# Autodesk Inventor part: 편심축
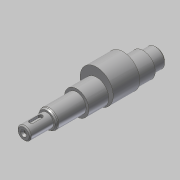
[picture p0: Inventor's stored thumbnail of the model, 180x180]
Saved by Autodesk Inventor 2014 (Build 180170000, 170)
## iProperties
Created: 2019-01
Part Number: 편심축
Material: 강철, 연강
Document SubType Name: Modeling
Designer: mduedu
Density: 7.86 g/cm^3
Appearance: 강철
Mass: 326.791 g
Surface Area: 90.982 cm^2
Volume: 41.5764 cm^3
Author: mduedu
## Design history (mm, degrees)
sketch "스케치1"
  geometry: L1 (0, 0)-(21, 0); L2 (21, 0)-(21, 6); L3 (21, 6)-(0, 6); L4 (0, 6)-(0, 0); L5 (21, 0)-(48, 0); L6 (48, 0)-(48, 8.5); L7 (48, 8.5)-(21, 8.5); L8 (21, 8.5)-(21, 0); L9 (48, 0)-(108, 0); L10 (108, 0)-(108, 11); L11 (108, 11)-(48, 11); L12 (48, 11)-(48, 0); L13 (108, 0)-(120, 0); L14 (120, 0)-(120, 8.5); L15 (120, 8.5)-(108, 8.5); L16 (108, 8.5)-(108, 0)
  constraints: 32 end point, 8 parallel, 4 horizontal, 4 perpendicular
  dimensions: "d0" = 120 distance between parallel lines of L14 L4; "d2" = 12 distance of L14.end L15.end; "d3" = 60 distance of L10.end L11.end; "d4" = 99 distance between parallel lines of L8 L14; "d5" = 12 diameter of L3 L1; "d6" = 17 diameter of L7 L5; "d7" = 17 diameter of L15 L13; "d8" = 22 diameter of L11 L9
revolve "회전1" sketch "스케치1" stored, may be unused: angle "d9" = 90 deg
node "작업 평면1"
sketch "스케치2"
  geometry: C1 r 15 at (0, 4); C2 r 11 at (0, 0) reference; 1 further point
  constraints: 1 centre point, 1 tangent, 1 vertical alignment
  dimensions: "d11" = 4 distance of point (0, 0) C1.centre
extrude "돌출1" join sketch "스케치2" distance "d12" = 24; taper "d13" = 0 deg
node "작업 평면2"
sketch "스케치3" dims "d16" = 12
  geometry: L1 (-4.5, 2)-(3.5, 2); L2 (3.5, 2)-(3.5, -2); L3 (3.5, -2)-(-4.5, -2); L4 (-4.5, -2)-(-4.5, 2); L5 (-10.5, 8.5)-(-10.5, -8.5) reference; 3 further points
  constraints: 8 end point, 2 midpoint, 2 parallel, 2 vertical alignment, 1 horizontal, 1 horizontal alignment, 1 perpendicular, 4 other
  dimensions: "d14" = 4 distance between parallel lines of L3 L1; "d17" = 4 dimension on L5
extrude "돌출2" cut sketch "스케치3" distance "d18" = 2.5; taper "d19" = 0 deg
chamfer "모따기1" distance "d20" = 1.82; stored, may be unused: second distance "d21" = 2, angle "d22" = 30 deg
fillet "모깎기1" dims "d23" = 2
hole "구멍2" diameter "d39" = 3.242; stored, may be unused: countersink angle "d43" = 60 deg, drill point angle "d45" = 118 deg; dims "d37" = 10, "d38" = 10, "d40" = 8, "d41" = 5.51, "d42" = 2, "d44" = 10
sketch "스케치5"
  geometry: L1 (0, 0)-(2, 0); L2 (2, 0)-(2, 1.621); L3 (0, 2.776)-(0, 0); L4 (0, 2.776)-(2, 1.621); L5 (10, 1.621)-(0, 1.621) reference
  constraints: 8 end point, 1 horizontal, 1 parallel, 1 perpendicular, 1 point on line
  dimensions: "d46" = 2 distance between parallel lines of L2 L3; "d48" = 30 deg angle of L4 L1
revolve "회전2" sketch "스케치5" stored, may be unused: angle "d50" = 90 deg
chamfer "모따기2" distance "d25" = 1; stored, may be unused: second distance "d26" = 2, angle "d27" = 30 deg
node "솔리드1"
